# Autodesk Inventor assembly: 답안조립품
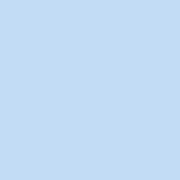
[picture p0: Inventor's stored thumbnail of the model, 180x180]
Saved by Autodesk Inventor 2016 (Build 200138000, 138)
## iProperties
Created: 2018-05
Part Number: 답안조립품
Document SubType Name: Assembly
Designer: 301-08
Author: 301-08
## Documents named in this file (1)
- C:\Users\301-08\Desktop\480507V1020\답안조립품.iam
